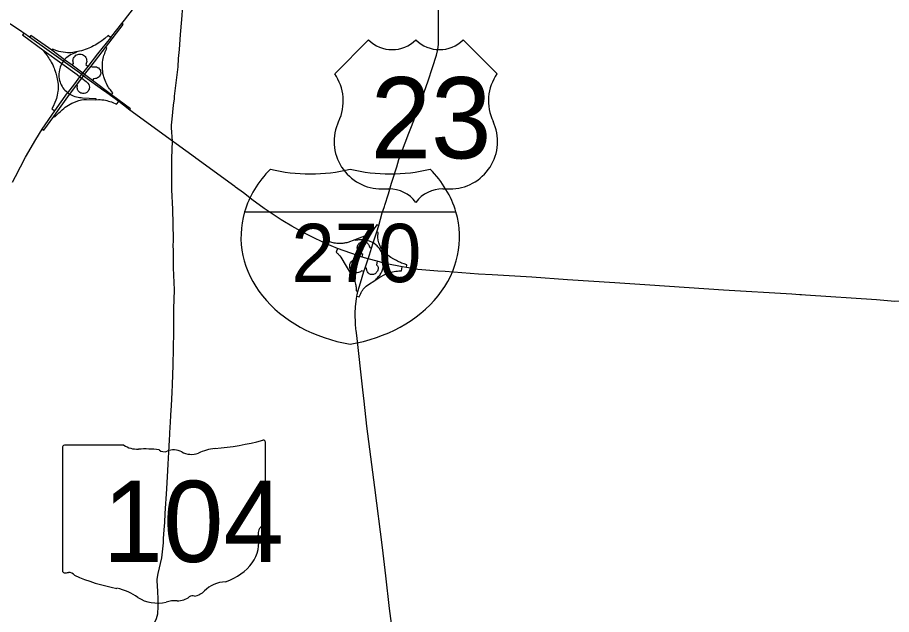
# Model space of a CAD drawing. Extents: x -7.1 to 34, y 0 to 22.
# Drawn here: x 5.069 to 6.456, y 15.086 to 16.034 of the extents above; entities that cross this region are included whole.
import ezdxf

# ---------------------------------------------------------------- set-up
doc = ezdxf.new("R2010")
doc.units = 0
for name, color, linetype in [('GM_X_Interchange_Ramps', 7, 'Continuous'), ('GM_X_Interstate_Route', 7, 'Continuous'), ('GM_X_Interstate_Shield', 7, 'Continuous'), ('GM_X_State_Route', 7, 'Continuous'), ('GM_X_State_Shield', 7, 'Continuous'), ('GM_X_US_Route', 7, 'Continuous'), ('GM_X_US_Shield', 7, 'Continuous')]:
    doc.layers.add(name, color=color, linetype=linetype)

msp = doc.modelspace()

# ---------------------------------------------------------------- linework, layer by layer
at = {"layer": 'GM_X_Interchange_Ramps'}
for points in [[(5.1079, 15.8562), (5.1104, 15.8545), (5.1262, 15.8767), (5.1324, 15.8855), (5.1511, 15.9115), (5.1515, 15.912), (5.1623, 15.9261), (5.1708, 15.9371), (5.1735, 15.9407), (5.1752, 15.9429), (5.1855, 15.9564), (5.2083, 15.986), (5.2362, 16.0223), (5.2343, 16.0238)], [(5.0785, 16.0089), (5.0763, 16.0058), (5.1107, 15.9809), (5.1389, 15.9605), (5.1631, 15.9429), (5.1678, 15.9394), (5.1708, 15.9371), (5.1776, 15.932), (5.1802, 15.9294), (5.1816, 15.9273), (5.1824, 15.925), (5.1827, 15.9228), (5.1824, 15.9205), (5.1821, 15.9192), (5.1815, 15.918), (5.1806, 15.9166), (5.1795, 15.9154), (5.1784, 15.9145), (5.1765, 15.9135), (5.1744, 15.913), (5.1723, 15.9129), (5.1705, 15.9132), (5.1692, 15.9137), (5.1675, 15.9146), (5.1661, 15.9159), (5.1649, 15.9174), (5.1641, 15.9191), (5.1637, 15.9206), (5.1635, 15.9221), (5.1636, 15.9251), (5.1623, 15.9261)], [(5.2467, 15.8865), (5.2482, 15.8885), (5.2179, 15.911), (5.1875, 15.9338), (5.1752, 15.9429), (5.1722, 15.9451), (5.1553, 15.9577), (5.1433, 15.9666), (5.1232, 15.9816), (5.0898, 16.0052), (5.0878, 16.0024)], [(5.2167, 16.0015), (5.2123, 16.005), (5.2071, 16.0003), (5.205, 15.9986), (5.2025, 15.9967), (5.1994, 15.9945), (5.1965, 15.9926), (5.1944, 15.9913), (5.192, 15.9898), (5.1894, 15.9885), (5.1868, 15.9871), (5.1845, 15.986), (5.182, 15.9849), (5.1793, 15.9838), (5.176, 15.9826), (5.1734, 15.9817), (5.17, 15.9807), (5.1672, 15.98), (5.1645, 15.9794), (5.1627, 15.979), (5.1611, 15.9788), (5.1592, 15.9784), (5.1565, 15.978), (5.1535, 15.9777), (5.1509, 15.9777), (5.1481, 15.9777), (5.1446, 15.9779), (5.1409, 15.9783), (5.1375, 15.9789), (5.134, 15.9798), (5.1308, 15.9807), (5.1243, 15.9831), (5.1232, 15.9816)], [(5.2179, 15.911), (5.2201, 15.9139), (5.2174, 15.917), (5.216, 15.9188), (5.2148, 15.9204), (5.2132, 15.9227), (5.212, 15.9245), (5.211, 15.9263), (5.2097, 15.9288), (5.2087, 15.9309), (5.2076, 15.9334), (5.2065, 15.9363), (5.2056, 15.9393), (5.205, 15.9416), (5.2043, 15.9447), (5.2038, 15.9483), (5.2035, 15.951), (5.2033, 15.9539), (5.2033, 15.9565), (5.2034, 15.9585), (5.2035, 15.9609), (5.2037, 15.9628), (5.2041, 15.9658), (5.2047, 15.9685), (5.2052, 15.9709), (5.2059, 15.9734), (5.207, 15.9765), (5.2079, 15.9789), (5.2104, 15.9844), (5.2083, 15.986)], [(5.1107, 15.9809), (5.1101, 15.98), (5.1155, 15.973), (5.1169, 15.9713), (5.1185, 15.9689), (5.1196, 15.9671), (5.121, 15.9648), (5.1223, 15.9625), (5.1237, 15.9599), (5.1245, 15.9582), (5.1257, 15.9555), (5.1266, 15.9533), (5.1274, 15.9512), (5.1283, 15.9484), (5.1292, 15.9452), (5.1298, 15.943), (5.1309, 15.939), (5.1317, 15.9358), (5.1322, 15.9335), (5.1326, 15.9306), (5.1329, 15.9279), (5.1331, 15.9242), (5.1331, 15.9213), (5.133, 15.9186), (5.1328, 15.9164), (5.1323, 15.9133), (5.1318, 15.9104), (5.1312, 15.9079), (5.1304, 15.9051), (5.1295, 15.9025), (5.1279, 15.8986), (5.1253, 15.8923), (5.1233, 15.8886), (5.128, 15.8853)], [(5.1611, 15.9788), (5.1614, 15.9774), (5.1592, 15.9768), (5.1562, 15.9759), (5.1537, 15.9748), (5.1514, 15.9734), (5.1488, 15.9717), (5.1468, 15.9701), (5.1455, 15.9689), (5.1439, 15.9673), (5.1433, 15.9666), (5.1426, 15.9658), (5.1412, 15.9641), (5.1409, 15.9637), (5.1394, 15.9614), (5.1389, 15.9605), (5.1382, 15.9593), (5.1373, 15.9573), (5.1363, 15.9549), (5.1356, 15.9528), (5.1351, 15.9507), (5.1345, 15.9471), (5.1342, 15.9441), (5.1342, 15.9417), (5.1344, 15.9392), (5.1348, 15.9364), (5.1354, 15.9335), (5.1362, 15.9309), (5.1371, 15.9286), (5.1381, 15.9265), (5.1393, 15.9243), (5.1407, 15.9221), (5.1423, 15.92), (5.1439, 15.9182), (5.1456, 15.9165), (5.1479, 15.9146), (5.1483, 15.9142), (5.1498, 15.9131), (5.1515, 15.912), (5.1525, 15.9114), (5.155, 15.9101), (5.1572, 15.9091), (5.1596, 15.9083), (5.1624, 15.9075), (5.1649, 15.9069), (5.1672, 15.9066), (5.1696, 15.9064), (5.1717, 15.9063), (5.1928, 15.9048), (5.1928, 15.9031)], [(5.1553, 15.9577), (5.1574, 15.9604), (5.1569, 15.9631), (5.1567, 15.9646), (5.1569, 15.9663), (5.1572, 15.9678), (5.1577, 15.9692), (5.1586, 15.9707), (5.16, 15.9724), (5.1613, 15.9735), (5.1628, 15.9744), (5.1643, 15.975), (5.1661, 15.9754), (5.168, 15.9755), (5.1698, 15.9753), (5.1716, 15.9747), (5.1734, 15.9738), (5.1749, 15.9727), (5.176, 15.9715), (5.1769, 15.9702), (5.1775, 15.969), (5.178, 15.9677), (5.1783, 15.9658), (5.1784, 15.9638), (5.1781, 15.9619), (5.1777, 15.9604), (5.1769, 15.9587), (5.1806, 15.9559)], [(5.1855, 15.9564), (5.1873, 15.955), (5.1907, 15.9555), (5.1921, 15.9554), (5.1941, 15.9551), (5.1958, 15.9544), (5.1973, 15.9534), (5.1985, 15.9522), (5.1994, 15.951), (5.2001, 15.9496), (5.2006, 15.9481), (5.2008, 15.9465), (5.2007, 15.9449), (5.2004, 15.9434), (5.1999, 15.942), (5.199, 15.9405), (5.1981, 15.9394), (5.1969, 15.9383), (5.1956, 15.9376), (5.1942, 15.937), (5.1925, 15.9366), (5.1894, 15.9364), (5.1875, 15.9338)], [(5.1262, 15.8767), (5.1277, 15.8757), (5.1309, 15.879), (5.134, 15.882), (5.1368, 15.8846), (5.1396, 15.8871), (5.1422, 15.8892), (5.1443, 15.891), (5.147, 15.893), (5.1494, 15.8945), (5.1547, 15.8975), (5.1579, 15.8989), (5.1617, 15.9004), (5.1658, 15.9016), (5.1704, 15.9027), (5.174, 15.9032), (5.177, 15.9035), (5.1783, 15.9036), (5.1928, 15.9031), (5.1974, 15.9032), (5.2, 15.9032), (5.2027, 15.9031), (5.2054, 15.9028), (5.2081, 15.9023), (5.2105, 15.9018), (5.2133, 15.901), (5.2154, 15.9004), (5.2176, 15.8996), (5.2208, 15.8983), (5.2235, 15.897), (5.2259, 15.8958), (5.2292, 15.9003)], [(5.6422, 15.7036), (5.639, 15.7044), (5.6348, 15.6985), (5.6337, 15.6971), (5.6325, 15.6958), (5.6313, 15.6945), (5.6298, 15.6931), (5.6285, 15.692), (5.6272, 15.691), (5.6258, 15.69), (5.6243, 15.689), (5.6222, 15.6878), (5.6043, 15.6808), (5.5932, 15.6766), (5.5911, 15.6761), (5.5895, 15.6758), (5.5879, 15.6755), (5.5864, 15.6753), (5.585, 15.6751), (5.5834, 15.6749), (5.5814, 15.6748), (5.5793, 15.6748), (5.5776, 15.6749), (5.5756, 15.675), (5.5734, 15.6753), (5.5713, 15.6756), (5.5694, 15.676), (5.5674, 15.6765), (5.5585, 15.6796), (5.5564, 15.6755)], [(5.6859, 15.6366), (5.6866, 15.6409), (5.6823, 15.6424), (5.6804, 15.6431), (5.6783, 15.6439), (5.6768, 15.6446), (5.6757, 15.6451), (5.6741, 15.6458), (5.6729, 15.6463), (5.6716, 15.647), (5.6703, 15.6477), (5.6659, 15.6499), (5.6613, 15.6529), (5.6592, 15.6543), (5.6569, 15.6559), (5.6552, 15.6573), (5.6536, 15.6588), (5.6519, 15.6605), (5.6502, 15.6623), (5.6493, 15.6634), (5.6481, 15.665), (5.6471, 15.6663), (5.6465, 15.6672), (5.645, 15.6696), (5.6434, 15.6732), (5.6428, 15.6747), (5.6423, 15.6761), (5.6417, 15.6782), (5.6413, 15.68), (5.641, 15.6815), (5.6408, 15.6835), (5.6407, 15.6856), (5.6412, 15.6925), (5.6392, 15.6932)], [(5.6376, 15.6172), (5.6371, 15.618), (5.6398, 15.6204), (5.6412, 15.6218), (5.6426, 15.6236), (5.6435, 15.6244), (5.6443, 15.6257), (5.6451, 15.6271), (5.646, 15.6287), (5.6467, 15.6302), (5.6473, 15.6318), (5.6479, 15.6333), (5.6495, 15.6386), (5.6502, 15.6437), (5.6502, 15.644), (5.65, 15.649), (5.6495, 15.6538), (5.6477, 15.6583), (5.6465, 15.6618), (5.6448, 15.6646), (5.6433, 15.6668), (5.6408, 15.6698), (5.6394, 15.6714), (5.6379, 15.6725), (5.6343, 15.6755), (5.6333, 15.6759), (5.631, 15.6769), (5.6284, 15.6779), (5.6271, 15.6785), (5.6254, 15.6791), (5.6238, 15.6796), (5.6217, 15.6802), (5.62, 15.6806), (5.6167, 15.681), (5.6147, 15.681), (5.6124, 15.6808), (5.6101, 15.6806), (5.6081, 15.6804), (5.6048, 15.6796), (5.6043, 15.6808)], [(5.6157, 15.6534), (5.6169, 15.6573), (5.6141, 15.6588), (5.6116, 15.6606), (5.6102, 15.6622), (5.6092, 15.6635), (5.6086, 15.6649), (5.6081, 15.6667), (5.608, 15.6681), (5.6081, 15.6695), (5.6084, 15.6709), (5.6089, 15.6722), (5.6094, 15.6733), (5.6102, 15.6744), (5.6111, 15.6753), (5.6122, 15.6762), (5.6134, 15.6769), (5.6148, 15.6774), (5.6163, 15.6777), (5.618, 15.6778), (5.6192, 15.6777), (5.6205, 15.6774), (5.6216, 15.6769), (5.6226, 15.6764), (5.6236, 15.6758), (5.6245, 15.6749), (5.6252, 15.6741), (5.6258, 15.6731), (5.6267, 15.6714), (5.6276, 15.6684), (5.6307, 15.6673)], [(5.5765, 15.6668), (5.5744, 15.6611), (5.5764, 15.6593), (5.5774, 15.6584), (5.5783, 15.6576), (5.5792, 15.6566), (5.5802, 15.6555), (5.5817, 15.6534), (5.6006, 15.6221), (5.6015, 15.6205), (5.6021, 15.6191), (5.6029, 15.6173), (5.6035, 15.6159), (5.6041, 15.6144), (5.6046, 15.6127), (5.6052, 15.6106), (5.6056, 15.6087), (5.6059, 15.607), (5.6061, 15.6055), (5.6063, 15.604), (5.6063, 15.5996), (5.609, 15.599)], [(5.6186, 15.6306), (5.6149, 15.6318), (5.613, 15.6302), (5.6114, 15.6292), (5.6099, 15.6287), (5.608, 15.6283), (5.6066, 15.6282), (5.6047, 15.6284), (5.6029, 15.6289), (5.6013, 15.6296), (5.5999, 15.6306), (5.5983, 15.6321), (5.5973, 15.6337), (5.5963, 15.636), (5.5959, 15.6381), (5.5959, 15.6401), (5.5962, 15.642), (5.5972, 15.6443), (5.5986, 15.6463), (5.6006, 15.6481), (5.6025, 15.6491), (5.6042, 15.6497), (5.6064, 15.65), (5.6082, 15.6557)], [(5.607, 15.5912), (5.611, 15.5904), (5.6134, 15.5957), (5.6143, 15.5974), (5.6154, 15.5992), (5.6163, 15.6006), (5.6175, 15.6023), (5.619, 15.604), (5.6207, 15.6058), (5.6221, 15.6072), (5.624, 15.6087), (5.6376, 15.6172), (5.6435, 15.6215), (5.6517, 15.6259), (5.6539, 15.6268), (5.6556, 15.6275), (5.6576, 15.6282), (5.6593, 15.6288), (5.6616, 15.6294), (5.6639, 15.63), (5.6667, 15.6305), (5.6693, 15.631), (5.6718, 15.6312), (5.6739, 15.6314), (5.678, 15.6316), (5.679, 15.6377)], [(5.6395, 15.6467), (5.6383, 15.6413), (5.6399, 15.6397), (5.641, 15.6372), (5.6411, 15.6351), (5.6408, 15.6328), (5.64, 15.6308), (5.6387, 15.6292), (5.638, 15.6283), (5.6371, 15.6275), (5.6361, 15.6267), (5.635, 15.6261), (5.6339, 15.6258), (5.6327, 15.6255), (5.6315, 15.6255), (5.6304, 15.6256), (5.6289, 15.6259), (5.6278, 15.6264), (5.6267, 15.627), (5.6257, 15.6278), (5.625, 15.6285), (5.6242, 15.6297), (5.6236, 15.6309), (5.6232, 15.6322), (5.6226, 15.6357), (5.6205, 15.6363)]]:
    msp.add_lwpolyline(points, dxfattribs=at)
at = {"layer": 'GM_X_Interstate_Route'}
for points in [[(5.2386, 16.0295), (5.2672, 16.0671)], [(5.0785, 16.0089), (5.0754, 16.011), (5.0574, 16.0229), (5.0439, 16.0309)], [(5.2343, 16.0238), (5.2385, 16.0294), (5.2386, 16.0295)], [(5.2185, 16.0038), (5.2343, 16.0238)], [(5.0878, 16.0024), (5.0785, 16.0089)], [(5.1705, 15.9429), (5.1412, 15.9641), (5.1411, 15.9642), (5.1042, 15.9906), (5.0986, 15.9946), (5.0878, 16.0024)], [(5.1705, 15.9429), (5.1722, 15.9451), (5.1806, 15.9559), (5.1961, 15.9759), (5.2167, 16.0015), (5.2185, 16.0038)], [(5.128, 15.8853), (5.1482, 15.9141), (5.1483, 15.9142), (5.1595, 15.9283), (5.1678, 15.9394), (5.1705, 15.9429)], [(5.2056, 15.9173), (5.1735, 15.9407), (5.1705, 15.9429)], [(5.3204, 15.8332), (5.3145, 15.8375), (5.2467, 15.8865), (5.2292, 15.9003), (5.2102, 15.9139), (5.2056, 15.9173)], [(5.1079, 15.8562), (5.128, 15.8853)], [(5.0609, 15.7724), (5.0655, 15.7812), (5.0815, 15.8118), (5.0979, 15.8401), (5.1079, 15.8562)], [(5.3519, 15.8103), (5.3511, 15.8109), (5.3204, 15.8332)], [(5.4147, 15.7644), (5.4136, 15.7652), (5.3519, 15.8103)], [(5.44, 15.7455), (5.4272, 15.7552), (5.4147, 15.7644)], [(5.4899, 15.7108), (5.4871, 15.7125), (5.4603, 15.7307), (5.4408, 15.7449), (5.44, 15.7455)], [(5.5765, 15.6668), (5.5564, 15.6755), (5.5349, 15.6858), (5.5218, 15.6925), (5.5043, 15.7022), (5.4899, 15.7108)], [(5.6107, 15.6549), (5.6082, 15.6557), (5.5765, 15.6668)], [(5.6252, 15.6506), (5.6157, 15.6534), (5.6107, 15.6549)], [(5.6548, 15.6427), (5.6514, 15.6434), (5.6502, 15.6437), (5.6395, 15.6467), (5.6252, 15.6506)], [(6.3105, 15.5936), (6.2975, 15.5946), (6.1894, 15.601), (6.0722, 15.609), (6.0166, 15.6125), (5.9418, 15.6172), (5.8848, 15.6213), (5.8219, 15.625), (5.8005, 15.6262), (5.7473, 15.6303), (5.7358, 15.6312), (5.7039, 15.6335), (5.6859, 15.6366), (5.679, 15.6377), (5.6548, 15.6427)], [(6.5376, 15.5925), (6.526, 15.5895), (6.513, 15.5868), (6.4939, 15.5841), (6.4831, 15.5835), (6.4614, 15.5831), (6.4322, 15.5853), (6.3196, 15.593), (6.3129, 15.5934), (6.3105, 15.5936)]]:
    msp.add_lwpolyline(points, dxfattribs=at)
at = {"layer": 'GM_X_Interstate_Shield'}
msp.add_line((5.7646, 15.7249), (5.429, 15.7249), dxfattribs=at)
msp.add_line((5.7646, 15.7249), (5.429, 15.7249), dxfattribs=at)
for centre, start_param, end_param in [((5.6402, 15.6853), 2.47259, 2.911027), ((5.5334, 15.9589), 4.415841, 5.008937), ((5.6602, 15.9589), 4.415841, 5.008937), ((5.5534, 15.6853), 0.230566, 0.669003), ((5.6402, 15.6853), 2.911027, 4.511031), ((5.5534, 15.6853), 4.913747, 6.513751)]:
    msp.add_ellipse(centre, major_axis=(0.2169, 0), ratio=0.8, start_param=start_param, end_param=end_param, dxfattribs=at)
at = {"layer": 'GM_X_State_Route'}
for points in [[(5.318, 15.9089), (5.3234, 15.9555), (5.3243, 15.9684), (5.3257, 15.983), (5.3273, 16.0063), (5.3294, 16.0302), (5.331, 16.0516), (5.331, 16.0516)], [(5.3136, 15.7857), (5.3137, 15.8096), (5.3137, 15.8103), (5.3145, 15.8375), (5.313, 15.8583), (5.3131, 15.8629), (5.3139, 15.872), (5.3163, 15.8942), (5.3176, 15.9047), (5.3178, 15.9076), (5.3179, 15.9083), (5.318, 15.9089)], [(5.316, 15.6667), (5.3159, 15.6691), (5.3161, 15.682), (5.3152, 15.7295), (5.3136, 15.76), (5.3136, 15.7841), (5.3136, 15.7847), (5.3136, 15.7857)], [(5.3147, 15.4511), (5.3158, 15.482), (5.3168, 15.5345), (5.317, 15.5711), (5.3178, 15.6015), (5.3163, 15.6363), (5.3161, 15.6656), (5.316, 15.6667)], [(5.3098, 15.3605), (5.3105, 15.3744), (5.3114, 15.3914), (5.3121, 15.402), (5.3121, 15.4027), (5.313, 15.4176), (5.3143, 15.4385), (5.3147, 15.4511)], [(5.3094, 15.3532), (5.3096, 15.356), (5.3098, 15.3605)], [(5.3057, 15.2855), (5.3058, 15.2858), (5.3074, 15.3145), (5.3079, 15.3246), (5.3094, 15.3532)], [(5.2912, 15.1213), (5.2911, 15.1225), (5.2902, 15.1401), (5.2904, 15.1423), (5.292, 15.1515), (5.2979, 15.1763), (5.3002, 15.1999), (5.3003, 15.207), (5.3012, 15.2204), (5.3026, 15.232), (5.303, 15.2464), (5.3057, 15.2855)], [(5.2632, 15.0361), (5.2636, 15.0372), (5.265, 15.0404), (5.2689, 15.0468), (5.2724, 15.0517), (5.2759, 15.0569), (5.2818, 15.0651), (5.2849, 15.071), (5.2892, 15.0799), (5.2911, 15.0872), (5.2919, 15.0987), (5.2917, 15.1129), (5.2912, 15.1213)]]:
    msp.add_lwpolyline(points, dxfattribs=at)
at = {"layer": 'GM_X_State_Shield'}
for p, q in [((5.462, 15.2573), (5.462, 15.3596)), ((5.1399, 15.3514), (5.1399, 15.1558)), ((5.2374, 15.3548), (5.1431, 15.3548)), ((5.462, 15.2573), (5.462, 15.2573))]:
    msp.add_line(p, q, dxfattribs=at)
for centre, major_axis, start_param, end_param in [((5.3473, 15.6214), (0.3416, 0), 4.814394, 5.042369), ((5.4585, 15.36), (0.00359, 0), 6.141152, 7.989035), ((5.1436, 15.3518), (0.00373, 0), 1.712693, 3.28349), ((5.2599, 15.3775), (0.0362, 0), 4.042523, 4.731795), ((5.2719, 15.245), (0.1299, 0), 1.404758, 1.657858), ((5.3014, 15.3528), (0.0104, 0), 3.836095, 5.185415), ((5.3167, 15.3302), (0.0217, 0), 0.950623, 2.079405), ((5.3447, 15.3612), (0.0261, 0), 4.081561, 5.145723), ((5.3909, 15.295), (0.0687, 0), 1.699011, 2.107814), ((5.4612, 15.2498), (0.00555, 0), 1.883978, 3.671073), ((5.4259, 15.2368), (0.0333, 0), 5.934695, 6.695948), ((5.4582, 15.2569), (0.00384, 0), 5.05454, 6.418171), ((5.4749, 15.2145), (0.0242, 0), 2.387724, 3.262537), ((5.3664, 15.2015), (0.0854, 0), 5.101752, 6.440018), ((5.1436, 15.1554), (0.00376, 0), 3.00124, 4.508301), ((5.1442, 15.1754), (0.0287, 0), 4.665946, 4.897461), ((5.1501, 15.1445), (0.0104, 0), 0.519207, 1.627899), ((5.2809, 15.3202), (0.2467, 0), 4.195997, 4.488961), ((5.4025, 15.1009), (0.0468, 0), 1.647645, 2.488434), ((5.2073, 15.0679), (0.0772, 0), 0.823519, 1.323587), ((5.3432, 15.1368), (0.0276, 0), 4.937069, 5.64225), ((5.2908, 15.1436), (0.049, 0), 4.026481, 4.996735), ((5.3191, 15.0759), (0.0402, 0), 1.495662, 1.94098), ((5.3227, 15.1289), (0.0261, 0), 4.691044, 5.507374), ((5.3463, 15.11), (0.00735, 0), 1.147584, 2.315152)]:
    msp.add_ellipse(centre, major_axis=major_axis, ratio=0.8, start_param=start_param, end_param=end_param, dxfattribs=at)
at = {"layer": 'GM_X_US_Route'}
for points in [[(5.7203, 15.9331), (5.7275, 15.9542), (5.7338, 15.9735), (5.7353, 15.9806), (5.7362, 15.986), (5.7368, 15.992), (5.7371, 16.0028), (5.7369, 16.0924), (5.737, 16.1088), (5.737, 16.1233), (5.7371, 16.1393), (5.7371, 16.1575), (5.737, 16.1723), (5.737, 16.1758), (5.7371, 16.1836), (5.7373, 16.1979), (5.7376, 16.2243), (5.7375, 16.2294), (5.7377, 16.2572), (5.7377, 16.2722), (5.7377, 16.2881), (5.7379, 16.314), (5.7379, 16.3182)], [(5.7044, 15.8879), (5.7107, 15.9055), (5.7142, 15.9151), (5.7203, 15.9331)], [(5.6993, 15.8745), (5.7032, 15.8845), (5.7044, 15.8879)], [(5.6898, 15.8499), (5.6939, 15.8606), (5.6993, 15.8745)], [(5.6639, 15.7752), (5.6639, 15.7752), (5.6705, 15.7968), (5.6738, 15.808), (5.6898, 15.8499)], [(5.6509, 15.7335), (5.6516, 15.7356), (5.6574, 15.7537), (5.6625, 15.7706), (5.6639, 15.7752)], [(5.6273, 15.6569), (5.6307, 15.6673), (5.6333, 15.6759), (5.6392, 15.6932), (5.6422, 15.7036), (5.6477, 15.7234), (5.6509, 15.7335)], [(5.6059, 15.5392), (5.605, 15.5477), (5.6045, 15.5639), (5.605, 15.5749), (5.6065, 15.5873), (5.607, 15.5912), (5.6076, 15.5936), (5.609, 15.599), (5.613, 15.6124), (5.6186, 15.6306), (5.6205, 15.6363), (5.6252, 15.6506)], [(5.6252, 15.6506), (5.6273, 15.6569)], [(5.6062, 15.5367), (5.6059, 15.5392)], [(5.6698, 14.9607), (5.6699, 14.9612), (5.6707, 14.9725), (5.6711, 14.9868), (5.6708, 14.996), (5.6704, 15.0034), (5.6693, 15.0215), (5.6636, 15.0601), (5.6591, 15.0955), (5.653, 15.1474), (5.6478, 15.1926), (5.6356, 15.2878), (5.6233, 15.3853), (5.6189, 15.4246), (5.6168, 15.4429), (5.607, 15.5289), (5.6062, 15.5367)]]:
    msp.add_lwpolyline(points, dxfattribs=at)
at = {"layer": 'GM_X_US_Shield'}
for p, q in [((5.6258, 15.9979), (5.5721, 15.9442)), ((5.8298, 15.9442), (5.7761, 15.9979)), ((5.6472, 15.7616), (5.658, 15.7616)), ((5.7439, 15.7616), (5.7546, 15.7616))]:
    msp.add_line(p, q, dxfattribs=at)
for centre, radius, start, end in [((5.6633, 16.0362), 0.0537, 225.573, 314.427), ((5.7385, 16.0362), 0.0537, 225.573, 314.427), ((5.5105, 15.9011), 0.0752, 334.5471, 35.0009), ((5.8913, 15.9011), 0.0752, 144.9991, 205.4529), ((5.6464, 15.8368), 0.0752, 154.8319, 270.6383), ((5.7554, 15.8368), 0.0752, 269.3617, 25.1681), ((5.658, 15.708), 0.0537, 36.8699, 90), ((5.7439, 15.708), 0.0537, 90, 143.1301)]:
    msp.add_arc(centre, radius, start, end, dxfattribs=at)

# ---------------------------------------------------------------- texts
at = {"layer": 'GM_X_Interstate_Shield'}
msp.add_text('270', height=0.09255, dxfattribs=at).set_placement((5.5033, 15.6136))
at = {"layer": 'GM_X_State_Shield'}
msp.add_text('104', height=0.12885, dxfattribs=at).set_placement((5.2039, 15.1696))
at = {"layer": 'GM_X_US_Shield'}
msp.add_text('23', height=0.12885, dxfattribs=at).set_placement((5.6292, 15.81))

doc.saveas('drawing.dxf')
